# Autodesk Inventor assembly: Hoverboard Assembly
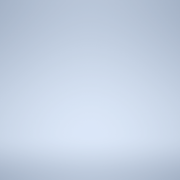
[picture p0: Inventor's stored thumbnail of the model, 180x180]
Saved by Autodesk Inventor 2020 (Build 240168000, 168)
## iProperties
Created: 2020-04
Part Number: Hoverboard Assembly
Document SubType Name: Assembly
Designer: bruno
Sending System: SolidWorks 2017
Last Author: hpras
Last Saved: 2020-04-24
Author: bruno
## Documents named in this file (1)
- C:\Users\bruno\Documents\1-Cours-2022-23\1SI\2. Cinématique\Hoverboard\Inventor-Hoverboard\Hoverboard Assembly.iam
